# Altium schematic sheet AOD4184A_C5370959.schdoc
size 127 x 101 mm
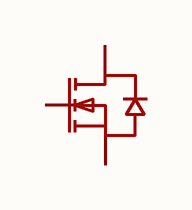
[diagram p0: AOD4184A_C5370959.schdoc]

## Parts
Q?  aod4184a_c5370959  [TO-252-3_L6.6-W6.1-P4.57-LS9.9-BR-CW]  (value not drawn)

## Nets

Not connected (* = marked no-connect by the designer): Q? 1(G) 2(D) 3(S)

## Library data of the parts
Q? = aod4184a_c5370959: 漏源电压(Vdss):40V;连续漏极电流(Id):53A;导通电阻(RDS(on)):17mΩ@4.5V,13A;耗散功率(Pd):30W;阈值电压(Vgs(th)):3V;; Manufacturer: TECH PUBLIC(台舟); AddInBom: yes; ModelId: dee852f3c6b348a2b9d5be5dd3244081; ModelTransform: 258.97184,390.1567,0,90,0,0,-35.433,0,0; Drain to Source Voltage: 40V; Current - Continuous Drain(Id): 53A; Pd - Power Dissipation: 30W; Gate Threshold Voltage (Vgs(th)@Id): 3V; Gate Charge(Qg): 18nC; Input Capacitance(Ciss@Vds): 1.5nF@20V; Reverse Transfer Capacitance (Crss@Vds): 60pF@20V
